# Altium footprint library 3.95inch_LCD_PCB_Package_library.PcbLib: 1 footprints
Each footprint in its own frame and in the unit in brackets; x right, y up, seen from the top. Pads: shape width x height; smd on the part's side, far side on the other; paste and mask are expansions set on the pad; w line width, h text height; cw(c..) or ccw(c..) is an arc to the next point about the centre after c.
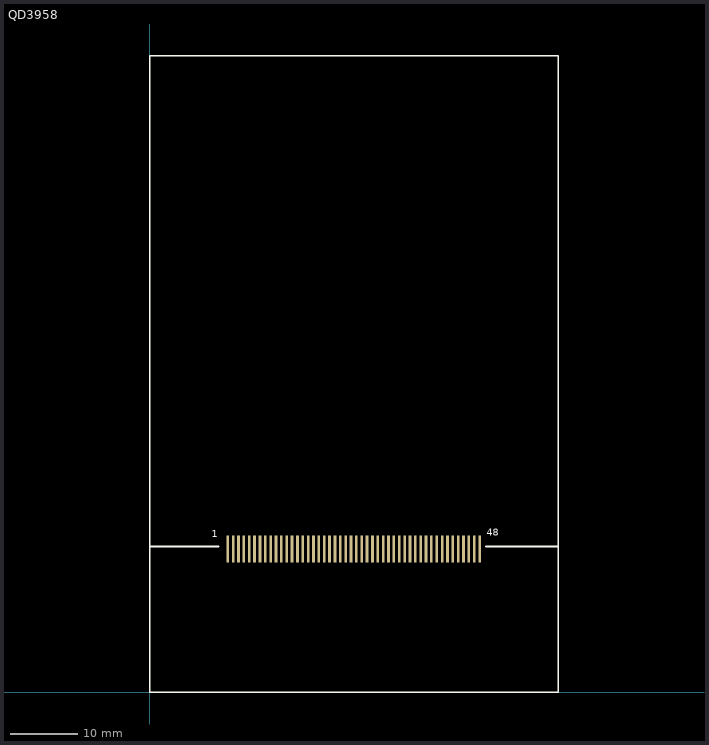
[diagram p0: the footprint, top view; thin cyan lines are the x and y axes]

## QD3958 [mm]
pads (48):
  rect 0.4x4 smd: 1(11.654,21.386) 2(12.454,21.386) 3(13.254,21.386) 4(14.054,21.386) 5(14.854,21.386) 6(15.654,21.386) 7(16.454,21.386) 8(17.254,21.386) 9(18.054,21.386) 10(18.854,21.386) 11(19.654,21.386) 12(20.454,21.386) 13(21.254,21.386) 14(22.054,21.386) 15(22.854,21.386) 16(23.654,21.386) 17(24.454,21.386) 18(25.254,21.386) 19(26.054,21.386) 20(26.854,21.386) 21(27.654,21.386) 22(28.454,21.386) 23(29.254,21.386) 24(30.054,21.386) 25(30.854,21.386) 26(31.654,21.386) 27(32.454,21.386) 28(33.254,21.386) 29(34.054,21.386) 30(34.854,21.386) 31(35.654,21.386) 32(36.454,21.386) 33(37.254,21.386) 34(38.054,21.386) 35(38.854,21.386) 36(39.654,21.386) 37(40.454,21.386) 38(41.254,21.386) 39(42.054,21.386) 40(42.854,21.386) 41(43.654,21.386) 42(44.454,21.386) 43(45.254,21.386) 44(46.054,21.386) 45(46.854,21.386) 46(47.654,21.386) 47(48.454,21.386) 48(49.254,21.386)
Top Overlay:
  lines w0.254: 0,21.762 10.289,21.762 ; 50.165,21.762 61,21.762 ; 0,0 0,95 61,95 61,0 0,0
  text "1" at 9.271,23.114 h1.02
  text "48" at 50.292,23.368 h1.02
